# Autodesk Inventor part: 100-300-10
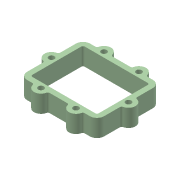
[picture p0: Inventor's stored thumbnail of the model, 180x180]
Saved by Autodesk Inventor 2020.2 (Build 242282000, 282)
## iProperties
Created: 2010-02
Part Number: 100-300-10
Material: Aluminium-6061
Document SubType Name: Modeling
Designer: F.Stasiak
Mass: 1814.06 g
Surface Area: 1195.54 cm^2
Volume: 669.396 cm^3
Density: 2.71 g/cm^3
Appearance: Zielony pastelowy
Manager: www.cadconsulting.pl
Company: Fabian Stasiak CAD Consulting
Author: F.Stasiak
Subject: Zbiór ćwiczeń. Autodesk Inventor 2020. Kurs podstawowy
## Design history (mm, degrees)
sketch "Szkic1"
  geometry: L1 (200, -75)-(20, -75); L2 (15, -70)-(15, 70); L3 (20, 75)-(200, 75); L4 (205, 70)-(205, -70); L5 (220, 70)-(220, 24.495); L6 (184.495, 90)-(200, 90); L7 (84.495, 90)-(135.505, 90); L8 (20, 90)-(35.505, 90); L9 (0, 24.495)-(0, 70); L10 (0, -70)-(0, -24.495); L11 (35.505, -90)-(20, -90); L12 (135.505, -90)-(84.495, -90); L13 (200, -90)-(184.495, -90); L14 (220, -24.495)-(220, -70); C1 r 8 at (160, 90); C2 r 8 at (60, 90); C3 r 8 at (0, 0); C4 r 8 at (60, -90); C5 r 8 at (160, -90); C6 r 8 at (220, 0); A1 r 5 centre (200, -70) between (200, -75) and (205, -70); A2 r 5 centre (20, -70) between (15, -70) and (20, -75); A3 r 5 centre (20, 70) between (20, 75) and (15, 70); A4 r 5 centre (200, 70) between (205, 70) and (200, 75); A5 r 20 centre (200, 70) between (220, 70) and (200, 90); A6 r 5 centre (184.495, 95) between (179.596, 94) and (184.495, 90); A7 r 20 centre (160, 90) between (179.596, 94) and (140.404, 94); A8 r 5 centre (135.505, 95) between (135.505, 90) and (140.404, 94); A9 r 5 centre (84.495, 95) between (79.596, 94) and (84.495, 90); A10 r 20 centre (60, 90) between (79.596, 94) and (40.404, 94); A11 r 5 centre (35.505, 95) between (35.505, 90) and (40.404, 94); A12 r 20 centre (20, 70) between (20, 90) and (0, 70); A13 r 5 centre (-5, 24.495) between (-4, 19.596) and (0, 24.495); A14 r 20 centre (0, 0) between (-4, 19.596) and (-4, -19.596); A15 r 5 centre (-5, -24.495) between (0, -24.495) and (-4, -19.596); A16 r 20 centre (20, -70) between (0, -70) and (20, -90); A17 r 5 centre (35.505, -95) between (40.404, -94) and (35.505, -90); A18 r 20 centre (60, -90) between (40.404, -94) and (79.596, -94); A19 r 5 centre (84.495, -95) between (84.495, -90) and (79.596, -94); A20 r 5 centre (135.505, -95) between (140.404, -94) and (135.505, -90); A21 r 20 centre (160, -90) between (140.404, -94) and (179.596, -94); A22 r 5 centre (184.495, -95) between (184.495, -90) and (179.596, -94); A23 r 20 centre (200, -70) between (200, -90) and (220, -70); A24 r 5 centre (225, -24.495) between (224, -19.596) and (220, -24.495); A25 r 20 centre (220, 0) between (224, -19.596) and (224, 19.596); A26 r 5 centre (225, 24.495) between (220, 24.495) and (224, 19.596); 1 further point
  constraints: 52 point on circle, 32 centre point, 28 end point, 5 equal radius
  dimensions: "d0" = 16 diameter of C6
extrude "Wyciągnięcie proste1" new body sketch "Szkic1" distance "d1" = 50; taper "d2" = 0 deg
node "Bryła1"
other parameters: "d8" = 0, "d9" = 0, "d10" = 0, "d11" = 0, "d12" = 0, "d13" = 0
